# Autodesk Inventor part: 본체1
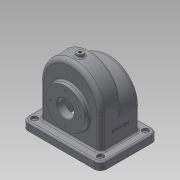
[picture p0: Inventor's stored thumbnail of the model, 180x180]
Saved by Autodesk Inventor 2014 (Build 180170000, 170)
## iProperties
Created: 2017-11
Part Number: 본체1
Material: Generic
Document SubType Name: Modeling
Designer: user
Density: 1 g/cm^3
Appearance: Default
Author: user
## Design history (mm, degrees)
sketch "스케치1"
  geometry: L1 (-58, 0)-(58, 0); L2 (58, 0)-(58, 80); L3 (58, 80)-(-58, 80); L4 (-58, 80)-(-58, 0); A1 r 58 centre (0, 80) between (58, 80) and (-58, 80); 2 further points
  constraints: 8 end point, 2 midpoint, 2 parallel, 2 point on circle, 1 centre point, 1 coincident, 1 horizontal, 1 perpendicular
  dimensions: "d0" = 116 distance of L2.end L3.end; "d1" = 80 distance of L3.end L1.start
extrude "돌출1" new body sketch "스케치1" distance "d3" = 38; taper "d4" = 0 deg
sketch "스케치2"
  geometry: L1 (-58, 57)-(-58, 0); L2 (58, 0)-(58, 57); L3 (-58, 0)-(58, 0) reference; L4 (-58, 57)-(58, 57); A1 r 58 centre (0, 57) between (58, 57) and (-58, 57); 1 further point
  constraints: 6 end point, 2 point on circle, 1 centre point, 1 midpoint, 1 perpendicular
  dimensions: "d5" = 57 distance between parallel lines of L3 L4
extrude "돌출2" join sketch "스케치2" distance "d7" = 38; taper "d8" = 0 deg
feature "쉘1" dims "d9" = 5
sketch "스케치3"
  geometry: L1 (5, -71)-(111, -71) reference; L2 (111, -71)-(111, -5) reference; L3 (111, -5)-(5, -5) reference; L4 (5, -5)-(5, -71) reference; L5 (116, -76)-(0, -76) reference; L6 (0, -76)-(0, 0) reference; L7 (0, 0)-(116, 0) reference; L8 (116, 0)-(116, -76) reference; L9 (133, 17)-(-17, 17); L10 (-17, 17)-(-17, -93); L11 (-17, -93)-(133, -93); L12 (133, -93)-(133, 17); L13 (133, 17)-(-17, -93); L14 (-17, 17)-(133, -93); 6 further points
  constraints: 12 end point, 6 midpoint, 2 parallel, 1 horizontal, 1 horizontal alignment, 1 perpendicular, 1 vertical alignment
  dimensions: "d10" = 110 distance of L11.end L9.start; "d11" = 150 distance of L10.end L11.end
extrude "돌출3" join sketch "스케치3" distance "d12" = 15; taper "d13" = 0 deg
fillet "모깎기1" dims "d14" = 12
sketch "스케치4"
  geometry: L1 (-17, -5)-(-17, 81) reference; L2 (-5, 93)-(121, 93) reference; L3 (58, 93)-(58, 55.72); L4 (-17, 38)-(19.739, 38); C1 r 10.105 at (-5, 81); A1 r 12 centre (-5, 81) between (-5, 93) and (-17, 81) reference; 5 further points
  constraints: 4 end point, 3 symmetric about line, 2 midpoint, 2 perpendicular, 1 centre point, 1 coincident, 1 concentric
  dimensions: "d15" = 20.20962 diameter of C1
hole "구멍1" sketch "스케치4" at (-5, 81), (121, 81), (-5, -5), (121, -5) diameter "d16" = 5; stored, may be unused: countersink angle "d20" = 90 deg, drill point angle "d22" = 0 deg; dims "d17" = 6, "d18" = 12, "d19" = 5, "d21" = 8
sketch "스케치5"
  geometry: L1 (63, 0)-(-63, 0) reference; C1 r 31 at (0, 65); 1 further point
  constraints: 1 centre point
  dimensions: "d23" = 65 distance from line of L1 C1.centre; "d24" = 62 diameter of C1
extrude "돌출4" join sketch "스케치5" distance "d25" = 10; taper "d26" = 0 deg
sketch "스케치6"
  geometry: C1 r 37.5 at (0, 65); C2 r 31 at (0, 65) reference; 1 further point
  constraints: 1 centre point, 1 concentric
  dimensions: "d27" = 75 diameter of C1
extrude "돌출5" join sketch "스케치6" distance "d28" = 9; taper "d29" = 0 deg
sketch "스케치7"
  geometry: L1 (102.5, 9)-(27.5, 9) reference; L2 (34, -86)-(96, -86) reference; L3 (65, 9)-(81, 9); L4 (81, 9)-(81, -5); L5 (81, -5)-(65, -5); L6 (65, -5)-(65, 9); L7 (0, -71)-(0, -5) reference; L8 (80, -5)-(0, -5) reference; L9 (65, -71)-(81, -71); L10 (81, -71)-(81, -86); L11 (81, -86)-(65, -86); L12 (65, -86)-(65, -71); L13 (0, -71)-(57, -71) reference; 1 further point
  constraints: 16 end point, 4 collinear, 4 parallel, 2 horizontal, 2 perpendicular, 1 midpoint, 1 point on line
  dimensions: "d30" = 65 distance between parallel lines of L7 L6; "d31" = 16 distance between parallel lines of L6 L4
revolve "회전1" sketch "스케치7" stored, may be unused: angle "d32" = 90 deg
sketch "스케치8"
  geometry: C1 r 37.5 at (0, 0) reference; A1 r 29 centre (0, 0) between (-29, 0) and (29, 0); 3 further points
  constraints: 4 point on circle, 1 centre point, 1 concentric
  dimensions: "d33" = 58 diameter of A1
hole "구멍2" sketch "스케치8" at (-29, 0), (29, 0), (0, 29), (0, -29) diameter "d34" = 2.459; stored, may be unused: countersink angle "d38" = 90 deg, drill point angle "d40" = 118 deg; dims "d35" = 6, "d36" = 12, "d37" = 5, "d39" = 8
sketch "스케치9"
  geometry: A1 r 26 centre (0, 0) between (0, 26) and (-26, 0); 3 further points
  constraints: 4 point on circle, 1 centre point
  dimensions: "d41" = 52 diameter of A1
hole "구멍3" sketch "스케치9" at (0, 26), (-26, 0), (26, 0), (0, -26) diameter "d42" = 2.459; stored, may be unused: countersink angle "d46" = 90 deg, drill point angle "d48" = 118 deg; dims "d43" = 6, "d44" = 12, "d45" = 5, "d47" = 8
node "작업 평면1"
sketch "스케치10"
  geometry: L1 (121, -17)-(5, -17) reference; C1 r 6 at (63, -36); 2 further points
  constraints: 1 centre point, 1 coincident, 1 midpoint, 1 vertical alignment
  dimensions: "d50" = 19 distance from line of C1.centre L1; "d51" = 12 diameter of C1
extrude "돌출6" join sketch "스케치10" stored distance "d52" = 9; taper "d53" = 0 deg
fillet "모깎기2" dims "d54" = 3
sketch "스케치11"
  geometry: C1 r 2.5 at (0, 0); C2 r 6 at (0, 0) reference; 1 further point
  constraints: 1 centre point, 1 concentric
  dimensions: "d55" = 5 diameter of C1
extrude "돌출7" cut sketch "스케치11" stored distance "d56" = 0; taper "d57" = 0 deg
feature "스레드1" dims "d58" = 10, "d59" = 0
sketch "스케치12"
  geometry: L1 (0, -65)-(0, 0) reference; L2 (-5, -80)-(-17, -80) reference; 2 further points
  constraints: 1 other
  dimensions: "d60" = 38 distance from line of point (38, -40) L1; "d61" = 40 distance from line of L2 point (38, -40)
feature "엠보싱1" sketch "스케치12" dims "d0" = 116, "d1" = 80, "d62" = 0.5, "d63" = 0
fillet "모깎기3" dims "d64" = 3
fillet "모깎기4" dims "d65" = 8
fillet "모깎기5" dims "d66" = 3
fillet "모깎기6" dims "d67" = 3
chamfer "모따기1" distance "d68" = 1; stored, may be unused: second distance "d69" = 2, angle "d70" = 45 deg
fillet "모깎기7" dims "d71" = 3
node "솔리드1"
node "절단 모서리 투영1"
other parameters: "d49" = -144
